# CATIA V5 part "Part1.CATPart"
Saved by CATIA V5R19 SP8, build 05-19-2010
Part number: Part1
Bounding box of the stored display mesh (mm): x 0 to 1220, y -2721.717 to 2163.003, z -2624.285 to 3071.723
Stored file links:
  C:\Users\ThinkMotion\Desktop\EU_thinkMotion\iao\IAO_MMS_Groupe3\gdespas\projet_Thinkmotion_GDESPAS\projet Thinkmotion GDESPAS\Assemblage gdespas\Part1.CATPart
  C:\Users\ThinkMotion\Desktop\EU_thinkMotion\iao\IAO_MMS_Groupe3\gdespas\projet_Thinkmotion_GDESPAS\projet Thinkmotion GDESPAS\Assemblage gdespas\Bielle2.CATPart
  C:\Users\ThinkMotion\Desktop\EU_thinkMotion\iao\IAO_MMS_Groupe3\gdespas\projet_Thinkmotion_GDESPAS\projet Thinkmotion GDESPAS\Assemblage gdespas\Assemblage IAO.CATProduct
  C:\Users\ThinkMotion\Desktop\EU_thinkMotion\iao\IAO_MMS_Groupe3\gdespas\projet_Thinkmotion_GDESPAS\projet Thinkmotion GDESPAS\Assemblage gdespas\pneu.CATPart
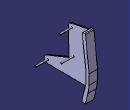
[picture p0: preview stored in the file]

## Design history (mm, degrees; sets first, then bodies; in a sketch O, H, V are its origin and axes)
External parameters (linked from other documents)
  External.diam_axe = 0.126
Set1
  DatumCurve1: linked copy from another document
Body1 (main body)
  Sketch1 on yz-plane, origin (0, 0, 0), H (0, 1, 0), V (0, 0, 1)
    line L1 (-2394.1556, -1788.4879) -> (1655.7389, -1817.7175)
    line L2 (-2449.6559, -1133.6125) -> (-421.9899, -287.2074)
    point P4 (-421.9899, -287.2074)
    line L3 (-476.3673, 2241.339) -> (-421.9899, -287.2074)
    point P5 (-421.9899, -287.2074)
    line L4 (-222.9479, 2559.7648) -> (1392.8981, 2895.5359)
    line L5 (1525.0516, 2986.9392) -> (1525.0516, 3057.9737)
    line L6 (1561.8451, 3032.1644) -> (1746.0609, 3070.4443)
    line L7 (1824.6722, 3013.4815) -> (2163.0027, 0)
    point P6 (2163.0027, 0)
    arc A1 centre (-158.2012, 2248.1813) radius 318.2396 from (-222.9479, 2559.7648) to (-476.3673, 2241.339) ccw
    arc A2 centre (1359.1437, 3057.9737) radius 165.9078 from (1525.0516, 3057.9737) to (1392.8981, 2895.5359) cw
    arc A3 centre (1571.2429, 2986.9392) radius 46.1913 from (1525.0516, 2986.9392) to (1561.8451, 3032.1644) cw
    arc A4 centre (1759.42, 3006.1554) radius 65.6622 from (1824.6722, 3013.4815) to (1746.0609, 3070.4443) ccw
    line L8 (2163.0027, 0) -> (2139.7599, -942.9602)
    line L9 (2046.3075, -1635.2104) -> (1800.3508, -2624.2846)
    arc A5 centre (-1054.0338, -864.2372) radius 3194.7638 from (2046.3075, -1635.2104) to (2139.7599, -942.9602) ccw
    line L10 (1495.5421, -2548.4867) -> (1800.3508, -2624.2846)
    line L11 (1495.5421, -2548.4867) -> (1655.7389, -1817.7175)
    arc A6 centre (-2391.7738, -1458.4965) radius 330 from (-2449.6559, -1133.6125) to (-2394.1556, -1788.4879) ccw
    reference intersected line E1 through (0, 0) direction (-1, 0) from xy-plane
    reference intersected line E2 through (0, 0) direction (0, 1) from zx-plane
    reference intersected line E3 through (0, 0) direction (0, 1) from zx-plane
    reference intersected line E4 through (0, 0) direction (-1, 0) from xy-plane
    point P24 (102.4864, 0)
    radius A1 = 318.2396
    radius A2 = 165.9078
    radius A3 = 46.1913
    radius A4 = 65.6622
    radius A5 = 3194.7638
    radius A6 = 330
    length L2 = 2197.2325
    length L3 = 2529.1311
    length L6 = 188.151
    length L7 = 3032.4146
    length L8 = 943.2466
    length L9 = 1019.197
    length L10 = 314.0918
    length L11 = 748.1221
    angle L1 E1 = 0.4135
    angle E2 L3 = 1.232
    angle L3 L2 = 111.4251
    distance A6 L2 = 7.8911
    distance P4 E3 = 421.9899
    distance P4 E4 = 287.2074
    angle L11 L1 = 78.0489
    distance A6 L1 = 0
    angle L10 L11 = 91.6001
    angle L4 L3 = 100.507
    length L4 = 1650.3638
    length L1 = 4050
    coincidence: P5 L2, L3 P4, P6 H, P4 P5, P24 H
    vertical: L5 V
    parallelism: L6 L4
    tangency: A1 L4, A1 L3, A2 L5, A2 L4, A3 L5, A3 L6, A4 L7, A4 L6, A5 L9, A5 L8
    perpendicularity: L10 L9
  Pad1: profile Sketch1, direction (1, 0, 0), length 800
  Sketch2 on end face of Pad1, origin (800, 0, 0), H (0, 1, 0), V (0, 0, 1)
    point P1 (1865.4832, -888.48)
    point P2 (1655.7389, -1817.7175)
    line L1 (1655.7389, -1817.7175) -> (1865.4832, -888.48)
    point P3 (1865.4832, -888.48)
    line L2 (1855.5426, 161.023) -> (1865.4832, -888.48)
    point P5 (1525.0516, 3057.9737)
    line L3 (1525.0516, 3057.9737) -> (1855.5426, 161.023)
    reference projected point E1 (1525.0516, 3057.9737) from vertex [face of Pad1 from Sketch1.A2 | end face of Pad1 | face of Pad1 from Sketch1.L5]
    reference projected point E2 (1655.7389, -1817.7175) from vertex [face of Pad1 from Sketch1.L11 | end face of Pad1 | face of Pad1 from Sketch1.L1]
    reference projected point E3 (1525.0516, 3057.9737) from vertex [face of Pad1 from Sketch1.A2 | end face of Pad1 | face of Pad1 from Sketch1.L5]
    length L2 = 1049.55
    length L3 = 2915.7414
    angle L3 L2 = 174.0344
    angle L2 L1 = 166.7379
    coincidence: L3 E1, P3 P1, P2 E2, P5 E3
  Pocket1: profile Sketch2, direction (-1, 0, 0), length 700
  Sketch3 on end face of Pocket1, origin (100, 0, 0), H (0, 1, 0), V (0, 0, 1)
    point P1 (-2391.7738, -1458.4965)
    circle A1 centre (-2391.7738, -1458.4965) radius 63
    point P2 (0, 0)
    circle A2 centre (0, 0) radius 63
    point P3 (-158.2012, 2248.1813)
    circle A3 centre (-158.2012, 2248.1813) radius 63
    reference intersected line E1 through (0, 0) direction (-1, 0) from xy-plane
    reference intersected line E2 through (0, 0) direction (-1, 0) from xy-plane
    reference intersected line E3 through (0, 0) direction (0, 1) from zx-plane
    reference intersected line E4 through (0, 0) direction (-1, 0) from xy-plane
    reference intersected line E5 through (0, 0) direction (-1, 0) from xy-plane
    reference intersected line E6 through (0, 0) direction (-1, 0) from xy-plane
    reference intersected line E7 through (0, 0) direction (0, 1) from zx-plane
    radius A1 = 63 {= External.diam_axe /2}
    radius A3 = 63 {= External.diam_axe /2}
    radius A2 = 63 {= External.diam_axe /2}
    distance P1 E1 = 1458.4965
    distance P2 E2 = 0
    distance E4 E5 = 0 (reference)
    distance P3 E6 = 2248.1813
    distance P3 E7 = 158.2012
    coincidence: P2 E3
  Pad2: profile Sketch3, direction (1, 0, 0), length 1120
